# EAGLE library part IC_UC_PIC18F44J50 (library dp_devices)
44-Pin Low Power USB Microcontrollers
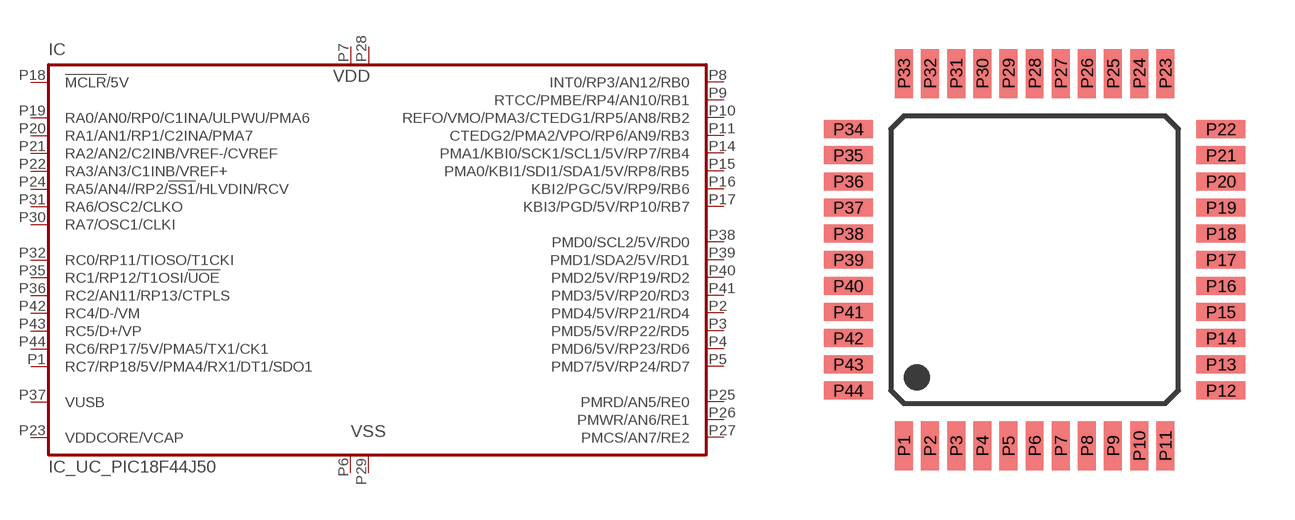
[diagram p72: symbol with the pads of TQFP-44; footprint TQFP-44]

Designator prefix IC

## IC_UC_PIC18F44J50  [TQFP-44]
P1  RC7/RP18/5V/PMA4/RX1/DT1/SDO1
P2  PMD4/5V/RP21/RD4
P3  PMD5/5V/RP22/RD5
P4  PMD6/5V/RP23/RD6
P5  PMD7/5V/RP24/RD7
P6  VSS  pwr
P7  VDD  pwr
P8  INT0/RP3/AN12/RB0
P9  RTCC/PMBE/RP4/AN10/RB1
P10  REFO/VMO/PMA3/CTEDG1/RP5/AN8/RB2
P11  CTEDG2/PMA2/VPO/RP6/AN9/RB3
P14  PMA1/KBI0/SCK1/SCL1/5V/RP7/RB4
P15  PMA0/KBI1/SDI1/SDA1/5V/RP8/RB5
P16  KBI2/PGC/5V/RP9/RB6
P17  KBI3/PGD/5V/RP10/RB7
P18  !MCLR!/5V  in
P19  RA0/AN0/RP0/C1INA/ULPWU/PMA6
P20  RA1/AN1/RP1/C2INA/PMA7
P21  RA2/AN2/C2INB/VREF-/CVREF
P22  RA3/AN3/C1INB/VREF+
P23  VDDCORE/VCAP  in
P24  RA5/AN4//RP2/!SS1!/HLVDIN/RCV
P25  PMRD/AN5/RE0
P26  PMWR/AN6/RE1
P27  PMCS/AN7/RE2
P28  VDD  pwr
P29  VSS  pwr
P30  RA7/OSC1/CLKI
P31  RA6/OSC2/CLKO
P32  RC0/RP11/TIOSO/T1CKI
P35  RC1/RP12/T1OSI/!UOE!
P36  RC2/AN11/RP13/CTPLS
P37  VUSB
P38  PMD0/SCL2/5V/RD0
P39  PMD1/SDA2/5V/RD1
P40  PMD2/5V/RP19/RD2
P41  PMD3/5V/RP20/RD3
P42  RC4/D-/VM
P43  RC5/D+/VP
P44  RC6/RP17/5V/PMA5/TX1/CK1

## Footprint TQFP-44 (pad centres in mm)
smd 0.55 x 1.5: P1 -4,-5.7; P2 -3.2,-5.7; P3 -2.4,-5.7; P4 -1.6,-5.7; P5 -0.8,-5.7; P6 0,-5.7; P7 0.8,-5.7; P8 1.6,-5.7; P9 2.4,-5.7; P10 3.2,-5.7; P11 4,-5.7; P23 4,5.7; P24 3.2,5.7; P25 2.4,5.7; P26 1.6,5.7; P27 0.8,5.7; P28 0,5.7; P29 -0.8,5.7; P30 -1.6,5.7; P31 -2.4,5.7; P32 -3.2,5.7; P33 -4,5.7
smd 1.5 x 0.55: P12 5.7,-4; P13 5.7,-3.2; P14 5.7,-2.4; P15 5.7,-1.6; P16 5.7,-0.8; P17 5.7,0; P18 5.7,0.8; P19 5.7,1.6; P20 5.7,2.4; P21 5.7,3.2; P22 5.7,4; P34 -5.7,4; P35 -5.7,3.2; P36 -5.7,2.4; P37 -5.7,1.6; P38 -5.7,0.8; P39 -5.7,0; P40 -5.7,-0.8; P41 -5.7,-1.6; P42 -5.7,-2.4; P43 -5.7,-3.2; P44 -5.7,-4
